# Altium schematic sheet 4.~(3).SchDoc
size 420 x 297 mm
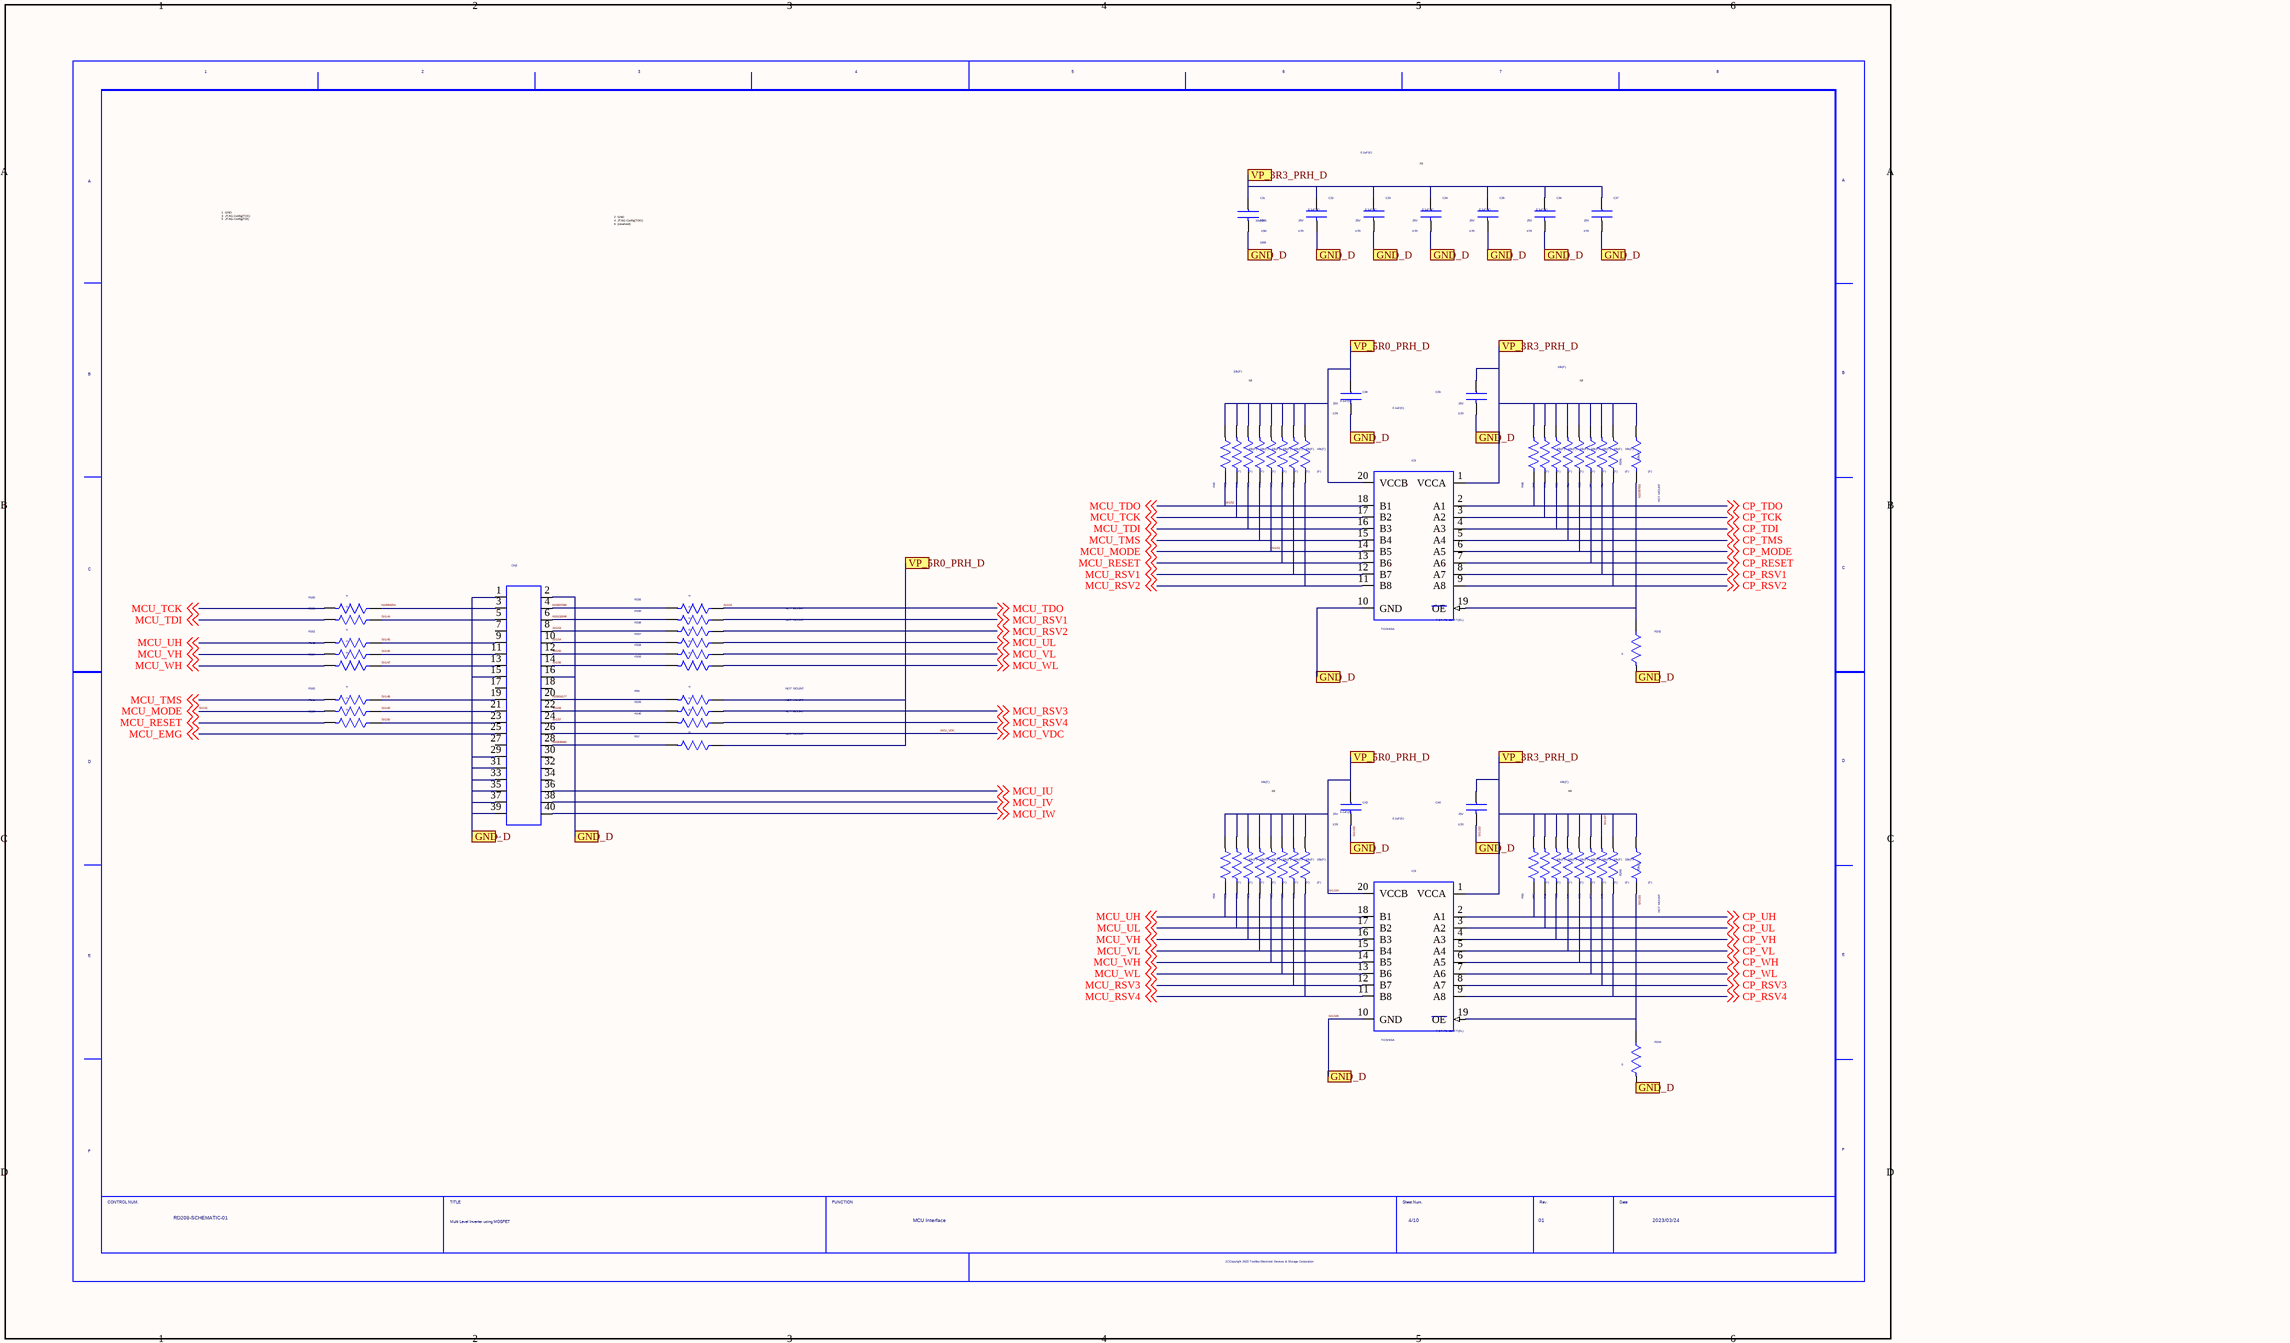
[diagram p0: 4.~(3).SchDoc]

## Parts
C31  VAL2: 10V  SIZECODESMD: 1608  VALUE4: X5R  VAL1: 10uF(M)  (hidden comment: GRM188R61A106ME69D)
C32  VAL2: 25V  VALUE4: X7R  VAL1: 0.1uF(K)  (hidden comment: GRM155R71E104KE14D)
C33  VAL2: 25V  VALUE4: X7R  VAL1: 0.1uF(K)  (hidden comment: GRM155R71E104KE14D)
C34  VAL2: 25V  VALUE4: X7R  VAL1: 0.1uF(K)  (hidden comment: GRM155R71E104KE14D)
C35  VAL2: 25V  VALUE4: X7R  VAL1: 0.1uF(K)  (hidden comment: GRM155R71E104KE14D)
C36  VAL2: 25V  VALUE4: X7R  VAL1: 0.1uF(K)  (hidden comment: GRM155R71E104KE14D)
C37  VAL2: 25V  VALUE4: X7R  VAL1: 0.1uF(K)  (hidden comment: GRM155R71E104KE14D)
C38  VAL2: 25V  VALUE4: X7R  VAL1: 0.1uF(K)  (hidden comment: GRM155R71E104KE14D)
C39  VAL2: 25V  VALUE4: X7R  VAL1: 0.1uF(K)  (hidden comment: GRM155R71E104KE14D)
C43  VAL2: 25V  VALUE4: X7R  VAL1: 0.1uF(K)  (hidden comment: GRM155R71E104KE14D)
C44  VAL2: 25V  VALUE4: X7R  VAL1: 0.1uF(K)  (hidden comment: GRM155R71E104KE14D)
CN3  VAL1: FTSH-120-04-F-DH-A  (hidden comment: FTSH_120_04_F_DH_A)
IC6  VAL1: TC7MPB9307FT(EL)  USERCOMPTEXT3: TOSHIBA  (hidden comment: TC7MPB9307FT)
IC8  VAL1: TC7MPB9307FT(EL)  USERCOMPTEXT3: TOSHIBA  (hidden comment: TC7MPB9307FT)
R40  VALUE4: (F)  VAL1: 10k(F)  (hidden comment: ERJ2RKF1002X)
R41  VALUE4: (F)  VAL1: 10k(F)  (hidden comment: ERJ2RKF1002X)
R42  VALUE4: (F)  VAL1: 10k(F)  (hidden comment: ERJ2RKF1002X)
R43  VALUE4: (F)  VAL1: 10k(F)  (hidden comment: ERJ2RKF1002X)
R44  VALUE4: (F)  VAL1: 10k(F)  (hidden comment: ERJ2RKF1002X)
R45  VALUE4: (F)  VAL1: 10k(F)  (hidden comment: ERJ2RKF1002X)
R46  VALUE4: (F)  VAL1: 10k(F)  (hidden comment: ERJ2RKF1002X)
R47  VALUE4: (F)  VAL1: 10k(F)  (hidden comment: ERJ2RKF1002X)
R48  VALUE4: (F)  VAL1: 10k(F)  (hidden comment: ERJ2RKF1002X)
R49  VALUE4: (F)  VAL1: 10k(F)  (hidden comment: ERJ2RKF1002X)
R50  VALUE4: (F)  VAL1: 10k(F)  (hidden comment: ERJ2RKF1002X)
R51  VALUE4: (F)  VAL1: 10k(F)  (hidden comment: ERJ2RKF1002X)
R52  VALUE4: (F)  VAL1: 10k(F)  (hidden comment: ERJ2RKF1002X)
R53  VALUE4: (F)  VAL1: 10k(F)  (hidden comment: ERJ2RKF1002X)
R54  VALUE4: (F)  VAL1: 10k(F)  (hidden comment: ERJ2RKF1002X)
R55  VALUE4: (F)  VAL1: 10k(F)  (hidden comment: ERJ2RKF1002X)
R56  VAL1: 0  NOTMOUNT: NOT MOUNT  (hidden comment: ERJ2GE0R00X)
R57  VAL1: 0  NOTMOUNT: NOT MOUNT  (hidden comment: ERJ2GE0R00X)
R58  VALUE4: (F)  VAL1: 10k(F)  (hidden comment: ERJ2RKF1002X)
R59  VALUE4: (F)  VAL1: 10k(F)  (hidden comment: ERJ2RKF1002X)
R60  VALUE4: (F)  VAL1: 10k(F)  (hidden comment: ERJ2RKF1002X)
R61  VALUE4: (F)  VAL1: 10k(F)  (hidden comment: ERJ2RKF1002X)
R62  VALUE4: (F)  VAL1: 10k(F)  (hidden comment: ERJ2RKF1002X)
R63  VALUE4: (F)  VAL1: 10k(F)  (hidden comment: ERJ2RKF1002X)
R64  VALUE4: (F)  VAL1: 10k(F)  (hidden comment: ERJ2RKF1002X)
R65  VALUE4: (F)  VAL1: 10k(F)  (hidden comment: ERJ2RKF1002X)
R66  VALUE4: (F)  VAL1: 10k(F)  (hidden comment: ERJ2RKF1002X)
R67  VALUE4: (F)  VAL1: 10k(F)  (hidden comment: ERJ2RKF1002X)
R68  VALUE4: (F)  VAL1: 10k(F)  (hidden comment: ERJ2RKF1002X)
R69  VALUE4: (F)  VAL1: 10k(F)  (hidden comment: ERJ2RKF1002X)
R70  VALUE4: (F)  VAL1: 10k(F)  (hidden comment: ERJ2RKF1002X)
R71  VALUE4: (F)  VAL1: 10k(F)  (hidden comment: ERJ2RKF1002X)
R72  VALUE4: (F)  VAL1: 10k(F)  (hidden comment: ERJ2RKF1002X)
R73  VALUE4: (F)  VAL1: 10k(F)  (hidden comment: ERJ2RKF1002X)
R156  VAL1: 0  (hidden comment: ERJ2GE0R00X)
R157  VAL1: 0  (hidden comment: ERJ2GE0R00X)
R158  VAL1: 0  (hidden comment: ERJ2GE0R00X)
R159  VAL1: 0  (hidden comment: ERJ2GE0R00X)
R160  VAL1: 0  (hidden comment: ERJ2GE0R00X)
R161  VAL1: 0  (hidden comment: ERJ2GE0R00X)
R162  VAL1: 0  (hidden comment: ERJ2GE0R00X)
R163  VAL1: 0  (hidden comment: ERJ2GE0R00X)
R164  VAL1: 0  (hidden comment: ERJ2GE0R00X)
R165  VAL1: 0  (hidden comment: ERJ2GE0R00X)
R166  VAL1: 0  (hidden comment: ERJ2GE0R00X)
R167  VAL1: 0  (hidden comment: ERJ2GE0R00X)
R198  VAL1: 0  NOTMOUNT: NOT MOUNT  (hidden comment: ERJ2GE0R00X)
R238  VAL1: 0  NOTMOUNT: NOT MOUNT  (hidden comment: ERJ2GE0R00X)
R239  VAL1: 0  NOTMOUNT: NOT MOUNT  (hidden comment: ERJ2GE0R00X)
R240  VAL1: 0  NOTMOUNT: NOT MOUNT  (hidden comment: ERJ2GE0R00X)
R241  VALUE4: (F)  VAL1: 10k(F)  NOTMOUNT: NOT MOUNT  (hidden comment: ERJ2RKF1002X)
R242  VAL1: 0  (hidden comment: ERJ2GE0R00X)
R243  VALUE4: (F)  VAL1: 10k(F)  NOTMOUNT: NOT MOUNT  (hidden comment: ERJ2RKF1002X)
R244  VAL1: 0  (hidden comment: ERJ2GE0R00X)
U?  DATE: 2023/03/24  TITLE: Multi Level Inverter using MOSFET  REVISION: 01  SHEETNUMBER: 4/10  DRAWINGNUMBER: RD208-SCHEMATIC-01  FUNCTION: MCU Interface  (hidden comment: WAKU_DEF100)

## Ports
GND_D, VP_3R3_PRH_D, VP_5R0_PRH_D

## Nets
CP_MODE: IC6.6(A5) R52.2 ; off-sheet CP_MODE
CP_RESET: IC6.7(A6) R53.2 ; off-sheet CP_RESET
CP_RSV1: IC6.8(A7) R54.2 ; off-sheet CP_RSV1
CP_RSV2: IC6.9(A8) R55.2 ; off-sheet CP_RSV2
CP_RSV3: IC8.8(A7) R72.2 ; off-sheet CP_RSV3
CP_RSV4: IC8.9(A8) R73.2 ; off-sheet CP_RSV4
CP_TCK: IC6.3(A2) R49.2 ; off-sheet CP_TCK
CP_TDI: IC6.4(A3) R50.2 ; off-sheet CP_TDI
CP_TDO: IC6.2(A1) R48.2 ; off-sheet CP_TDO
CP_TMS: IC6.5(A4) R51.2 ; off-sheet CP_TMS
CP_UH: IC8.2(A1) R66.2 ; off-sheet CP_UH
CP_UL: IC8.3(A2) R67.2 ; off-sheet CP_UL
CP_VH: IC8.4(A3) R68.2 ; off-sheet CP_VH
CP_VL: IC8.5(A4) R69.2 ; off-sheet CP_VL
CP_WH: IC8.6(A5) R70.2 ; off-sheet CP_WH
CP_WL: IC8.7(A6) R71.2 ; off-sheet CP_WL
MCU_EMG: CN3.25 ; off-sheet MCU_EMG
MCU_IU: CN3.36 ; off-sheet MCU_IU
MCU_IV: CN3.38 ; off-sheet MCU_IV
MCU_IW: CN3.40 ; off-sheet MCU_IW
MCU_RESET: IC6.13(B6) R45.2 R167.1 ; off-sheet MCU_RESET
MCU_RSV1: IC6.12(B7) R46.2 R198.2 ; off-sheet MCU_RSV1
MCU_RSV2: IC6.11(B8) R47.2 R238.2 ; off-sheet MCU_RSV2
MCU_RSV3: IC8.12(B7) R64.2 R239.2 ; off-sheet MCU_RSV3
MCU_RSV4: IC8.11(B8) R65.2 R240.2 ; off-sheet MCU_RSV4
MCU_TCK: IC6.17(B2) R41.2 R160.1 ; off-sheet MCU_TCK
MCU_TDI: IC6.16(B3) R42.2 R161.1 ; off-sheet MCU_TDI
MCU_TMS: IC6.15(B4) R43.2 R165.1 ; off-sheet MCU_TMS
MCU_UH: IC8.18(B1) R58.2 R162.1 ; off-sheet MCU_UH
MCU_UL: IC8.17(B2) R59.2 R157.2 ; off-sheet MCU_UL
MCU_VDC: CN3.26 ; off-sheet MCU_VDC
MCU_VH: IC8.16(B3) R60.2 R163.1 ; off-sheet MCU_VH
MCU_VL: IC8.15(B4) R61.2 R158.2 ; off-sheet MCU_VL
MCU_WH: IC8.14(B5) R62.2 R164.1 ; off-sheet MCU_WH
MCU_WL: IC8.13(B6) R63.2 R159.2 ; off-sheet MCU_WL
N15787951: IC6.19(OE) R241.2 R242.2
N15816177: CN3.20 R56.1
N15836565: CN3.28 R57.1
N15837096: CN3.4 R156.1
N16084254: CN3.3 R160.2
N16132048: CN3.6 R198.1
SIG44: CN3.5 R161.2
SIG45: CN3.9 R162.2
SIG46: CN3.11 R163.2
SIG47: CN3.13 R164.2
SIG48: CN3.19 R165.2
SIG49: CN3.21 R166.2
SIG50: CN3.23 R167.2
SIG51: IC6.14(B5) R44.2 R166.1 ; off-sheet MCU_MODE  [also labelled MCU_MODE]
SIG52: IC6.18(B1) R40.2 R156.2 ; off-sheet MCU_TDO  [also labelled MCU_TDO]
SIG53: CN3.8 R238.1
SIG54: CN3.10 R157.1
SIG55: CN3.12 R158.1
SIG56: CN3.14 R159.1
SIG57: CN3.24 R240.1
SIG58: CN3.22 R239.1
SIG101: IC8.19(OE) R243.2 R244.2
SIG102: C31.1 C31.2 C32.1 C32.2 C33.1 C33.2 C34.1 C34.2 C35.1 C35.2 C36.1 C36.2 C37.1 C37.2 C38.2 C39.1 C39.2 C43.2 C44.1 C44.2 CN3.1 CN3.2 CN3.15 CN3.16 CN3.29 CN3.31 CN3.33 CN3.35 CN3.37 CN3.39 IC6.1(VCCA) IC6.10(GND) IC8.1(VCCA) IC8.10(GND) R48.1 R49.1 R50.1 R51.1 R52.1 R53.1 R54.1 R55.1 R66.1 R67.1 R68.1 R69.1 R70.1 R71.1 R72.1 R73.1 R241.1 R242.1 R243.1 R244.1 ; port GND_D, port VP_3R3_PRH_D  [also labelled SIG103, SIG106, SIG107]
SIG104: C38.1 C43.1 IC6.20(VCCB) IC8.20(VCCB) R40.1 R41.1 R42.1 R43.1 R44.1 R45.1 R46.1 R47.1 R56.2 R57.2 R58.1 R59.1 R60.1 R61.1 R62.1 R63.1 R64.1 R65.1 ; port VP_5R0_PRH_D

Not connected (* = marked no-connect by the designer): CN3 7 17 18 27 30 32 34

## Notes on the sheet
- X6
- 1  GND
  3  JTAG-Config(TCK)
  5  JTAG-Config(TDI)
  7  (n.c.)
  9  High-side gate driver signal (U-Phase)
  11  High-side gate driver signal (V-Phase)
  13  High-side gate driver signal (W-Phase)
  15  GND
  17  (n.c.)
  19  JTAG-Config(TMS)
  21  CPLD-MODE
  23  CPLD-RESET
  25  EMG
  27  (n.c.)
  29  GND
  31  GND
  33  GND
  35  GND
  37  GND
  39  GND
- 2  GND
  4  JTAG-Config(TDO)
  6  (reserved)
  8  (reserved)
  10  Low-side gate driver signal (U-Phase)
  12  Low-side gate driver signal (V-Phase)
  14  Low-side gate driver signal (W-Phase)
  16  GND
  18  (n.c.)
  20  5V Input
  22  (reserved)
  24  (reserved)
  26  Inverter bus voltage divider voltage (Vdc)
  28  5V Input
  30  (n.c.)
  32  (n.c.)
  34  (n.c.)
  36  U-phase current value
  38  V-phase current value
  40  W-phase current value
- X8

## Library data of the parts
C31 = GRM188R61A106ME69D: MANUFACTURER: MURATA; ITEM: CAP Ceramic; TIME: 08:44:46; UPDATEUSER: t5459927; SAVECOUNT: 1; OriginalSymbolOrigin: (0,0); INSTANCENAME: INS15850047
C32 = GRM155R71E104KE14D: MANUFACTURER: MURATA; ITEM: CAP Ceramic; SIZECODESMD: 1005; TIME: 08:44:45; UPDATEUSER: t5459927; SAVECOUNT: 1; OriginalSymbolOrigin: (0,0); INSTANCENAME: INS15848437
C33 = GRM155R71E104KE14D: MANUFACTURER: MURATA; ITEM: CAP Ceramic; SIZECODESMD: 1005; TIME: 08:44:45; UPDATEUSER: t5459927; SAVECOUNT: 1; OriginalSymbolOrigin: (0,0); INSTANCENAME: INS15848594
C34 = GRM155R71E104KE14D: MANUFACTURER: MURATA; ITEM: CAP Ceramic; SIZECODESMD: 1005; TIME: 08:44:45; UPDATEUSER: t5459927; SAVECOUNT: 1; OriginalSymbolOrigin: (0,0); INSTANCENAME: INS15848750
C35 = GRM155R71E104KE14D: MANUFACTURER: MURATA; ITEM: CAP Ceramic; SIZECODESMD: 1005; TIME: 08:44:45; UPDATEUSER: t5459927; SAVECOUNT: 1; OriginalSymbolOrigin: (0,0); INSTANCENAME: INS15848907
C36 = GRM155R71E104KE14D: MANUFACTURER: MURATA; ITEM: CAP Ceramic; SIZECODESMD: 1005; TIME: 08:44:45; UPDATEUSER: t5459927; SAVECOUNT: 1; OriginalSymbolOrigin: (0,0); INSTANCENAME: INS15849085
C37 = GRM155R71E104KE14D: MANUFACTURER: MURATA; ITEM: CAP Ceramic; SIZECODESMD: 1005; TIME: 08:44:45; UPDATEUSER: t5459927; SAVECOUNT: 1; OriginalSymbolOrigin: (0,0); INSTANCENAME: INS15849105
C38 C43 = GRM155R71E104KE14D: MANUFACTURER: MURATA; ITEM: CAP Ceramic; SIZECODESMD: 1005; TIME: 08:44:45; UPDATEUSER: t5459927; SAVECOUNT: 1; OriginalSymbolOrigin: (0,0); INSTANCENAME: INS15846963
C39 C44 = GRM155R71E104KE14D: MANUFACTURER: MURATA; ITEM: CAP Ceramic; SIZECODESMD: 1005; TIME: 08:44:45; UPDATEUSER: t5459927; SAVECOUNT: 1; OriginalSymbolOrigin: (0,0); INSTANCENAME: INS15846983
CN3 = FTSH_120_04_F_DH_A: MANUFACTURER: Samtec; COMP: FTSH-120-04-F-DH-A-AEP; ITEM: Connector; TIME: 08:44:46; UPDATEUSER: t5459927; SAVECOUNT: 1; SAVEAREA0: -36272,-54408,42126,2984; OriginalSymbolOrigin: (0,0); INSTANCENAME: INS16810272
IC6 IC8 = TC7MPB9307FT: ITEM: IC BUS SW; VAL2: BUS SW; TIME: 08:44:46; UPDATEUSER: PS4_common_PC; UPDATETIME: 15:59:21; SAVECOUNT: 4; SAVEAREA0: -17429,-46731,34553,-8676; OriginalSymbolOrigin: (0,0)
R40 R58 = ERJ2RKF1002X: MANUFACTURER: Panasonic; ITEM: Register; VAL2: 100mW; SIZECODESMD: 1005; TIME: 08:44:45; UPDATEUSER: t5459927; SAVECOUNT: 1; OriginalSymbolOrigin: (0,0); INSTANCENAME: INS15795606
R41 R59 = ERJ2RKF1002X: MANUFACTURER: Panasonic; ITEM: Register; VAL2: 100mW; SIZECODESMD: 1005; TIME: 08:44:45; UPDATEUSER: t5459927; SAVECOUNT: 1; OriginalSymbolOrigin: (0,0); INSTANCENAME: INS17125057
R42 R60 = ERJ2RKF1002X: MANUFACTURER: Panasonic; ITEM: Register; VAL2: 100mW; SIZECODESMD: 1005; TIME: 08:44:45; UPDATEUSER: t5459927; SAVECOUNT: 1; OriginalSymbolOrigin: (0,0); INSTANCENAME: INS17125150
R43 R61 = ERJ2RKF1002X: MANUFACTURER: Panasonic; ITEM: Register; VAL2: 100mW; SIZECODESMD: 1005; TIME: 08:44:45; UPDATEUSER: t5459927; SAVECOUNT: 1; OriginalSymbolOrigin: (0,0); INSTANCENAME: INS17125244
R44 R62 = ERJ2RKF1002X: MANUFACTURER: Panasonic; ITEM: Register; VAL2: 100mW; SIZECODESMD: 1005; TIME: 08:44:45; UPDATEUSER: t5459927; SAVECOUNT: 1; OriginalSymbolOrigin: (0,0); INSTANCENAME: INS17125339
R45 R63 = ERJ2RKF1002X: MANUFACTURER: Panasonic; ITEM: Register; VAL2: 100mW; SIZECODESMD: 1005; TIME: 08:44:45; UPDATEUSER: t5459927; SAVECOUNT: 1; OriginalSymbolOrigin: (0,0); INSTANCENAME: INS17125433
R46 R64 = ERJ2RKF1002X: MANUFACTURER: Panasonic; ITEM: Register; VAL2: 100mW; SIZECODESMD: 1005; TIME: 08:44:45; UPDATEUSER: t5459927; SAVECOUNT: 1; OriginalSymbolOrigin: (0,0); INSTANCENAME: INS17125527
R47 R65 = ERJ2RKF1002X: MANUFACTURER: Panasonic; ITEM: Register; VAL2: 100mW; SIZECODESMD: 1005; TIME: 08:44:45; UPDATEUSER: t5459927; SAVECOUNT: 1; OriginalSymbolOrigin: (0,0); INSTANCENAME: INS17125624
R48 R66 = ERJ2RKF1002X: MANUFACTURER: Panasonic; ITEM: Register; VAL2: 100mW; SIZECODESMD: 1005; TIME: 08:44:45; UPDATEUSER: t5459927; SAVECOUNT: 1; OriginalSymbolOrigin: (0,0); INSTANCENAME: INS17126711
R49 R67 = ERJ2RKF1002X: MANUFACTURER: Panasonic; ITEM: Register; VAL2: 100mW; SIZECODESMD: 1005; TIME: 08:44:45; UPDATEUSER: t5459927; SAVECOUNT: 1; OriginalSymbolOrigin: (0,0); INSTANCENAME: INS17126722
R50 R68 = ERJ2RKF1002X: MANUFACTURER: Panasonic; ITEM: Register; VAL2: 100mW; SIZECODESMD: 1005; TIME: 08:44:45; UPDATEUSER: t5459927; SAVECOUNT: 1; OriginalSymbolOrigin: (0,0); INSTANCENAME: INS17126733
R51 R69 = ERJ2RKF1002X: MANUFACTURER: Panasonic; ITEM: Register; VAL2: 100mW; SIZECODESMD: 1005; TIME: 08:44:45; UPDATEUSER: t5459927; SAVECOUNT: 1; OriginalSymbolOrigin: (0,0); INSTANCENAME: INS17126744
R52 R70 = ERJ2RKF1002X: MANUFACTURER: Panasonic; ITEM: Register; VAL2: 100mW; SIZECODESMD: 1005; TIME: 08:44:45; UPDATEUSER: t5459927; SAVECOUNT: 1; OriginalSymbolOrigin: (0,0); INSTANCENAME: INS17126755
R53 R71 = ERJ2RKF1002X: MANUFACTURER: Panasonic; ITEM: Register; VAL2: 100mW; SIZECODESMD: 1005; TIME: 08:44:45; UPDATEUSER: t5459927; SAVECOUNT: 1; OriginalSymbolOrigin: (0,0); INSTANCENAME: INS17126766
R54 R72 = ERJ2RKF1002X: MANUFACTURER: Panasonic; ITEM: Register; VAL2: 100mW; SIZECODESMD: 1005; TIME: 08:44:45; UPDATEUSER: t5459927; SAVECOUNT: 1; OriginalSymbolOrigin: (0,0); INSTANCENAME: INS17126777
R55 R73 = ERJ2RKF1002X: MANUFACTURER: Panasonic; ITEM: Register; VAL2: 100mW; SIZECODESMD: 1005; TIME: 08:44:45; UPDATEUSER: t5459927; SAVECOUNT: 1; OriginalSymbolOrigin: (0,0); INSTANCENAME: INS17126788
R56 R57 = ERJ2GE0R00X: MANUFACTURER: Panasonic; ITEM: Register; VAL2: 1/10W; SIZECODESMD: 1005; TIME: 08:44:45; UPDATEUSER: t5459927; SAVECOUNT: 1; OriginalSymbolOrigin: (0,0); INSTANCENAME: INS17265222
R156-R159 = ERJ2GE0R00X: MANUFACTURER: Panasonic; ITEM: Register; VAL2: 1/10W; SIZECODESMD: 1005; TIME: 08:44:45; UPDATEUSER: t5459927; SAVECOUNT: 1; OriginalSymbolOrigin: (0,0); INSTANCENAME: INS16082588
R160-R167 = ERJ2GE0R00X: MANUFACTURER: Panasonic; ITEM: Register; VAL2: 1/10W; SIZECODESMD: 1005; TIME: 08:44:45; UPDATEUSER: t5459927; SAVECOUNT: 1; OriginalSymbolOrigin: (0,0); INSTANCENAME: INS16084230
R198 R238-R240 = ERJ2GE0R00X: MANUFACTURER: Panasonic; ITEM: Register; VAL2: 1/10W; SIZECODESMD: 1005; TIME: 08:44:45; UPDATEUSER: t5459927; SAVECOUNT: 1; OriginalSymbolOrigin: (0,0); INSTANCENAME: INS16693080
R241 R243 = ERJ2RKF1002X: MANUFACTURER: Panasonic; ITEM: Register; VAL2: 100mW; SIZECODESMD: 1005; TIME: 08:44:45; UPDATEUSER: t5459927; SAVECOUNT: 1; OriginalSymbolOrigin: (0,0); INSTANCENAME: INS16663974
R242 R244 = ERJ2GE0R00X: MANUFACTURER: Panasonic; ITEM: Register; VAL2: 1/10W; SIZECODESMD: 1005; TIME: 08:44:45; UPDATEUSER: t5459927; SAVECOUNT: 1; OriginalSymbolOrigin: (0,0); INSTANCENAME: INS16664582
U? = WAKU_DEF100: PLOTTIME: HH:MM; SAVEAREA0: 185750,-43960,448537,75779; TIME: 14:30:25; UPDATEUSER: PS4_common_PC; UPDATETIME: 08:24:35; SAVECOUNT: 8; OriginalSymbolOrigin: (10160,284480)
